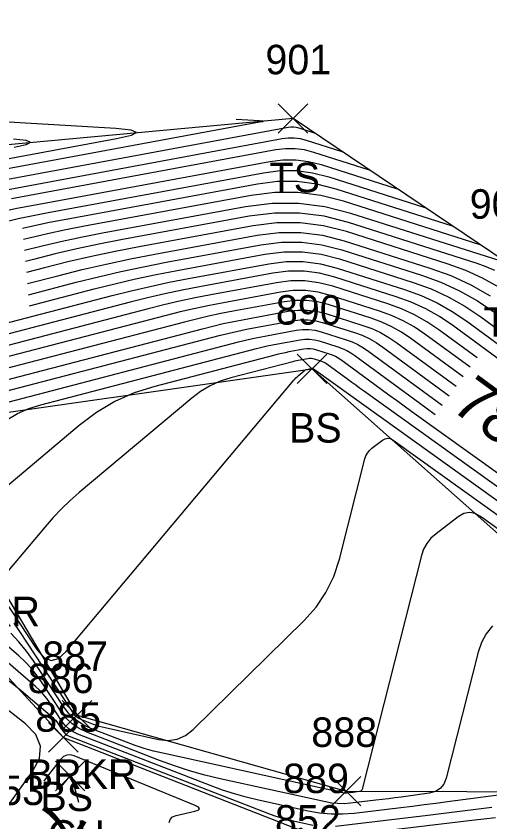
# Model space of a CAD drawing. Extents: x 1650836 to 1652450, y 332578 to 333908.
# Drawn here: x 1652201.2 to 1652233.3, y 332848.3 to 332902.9 of the extents above; entities that cross this region are included whole.
import ezdxf

# ---------------------------------------------------------------- set-up
doc = ezdxf.new("R2010")
doc.units = 0
for name, color, linetype in [('L_A', 7, 'Continuous'), ('L_I', 7, 'Continuous'), ('L_TIC', 7, 'Continuous'), ('LAWE', 7, 'Continuous'), ('LELB', 7, 'Continuous'), ('LSOGCMA', 7, 'Continuous'), ('LSOGCMA_T', 7, 'Continuous'), ('LSOGCMI', 7, 'Continuous'), ('LSOGP', 7, 'Continuous')]:
    doc.layers.add(name, color=color, linetype=linetype)

msp = doc.modelspace()

# ---------------------------------------------------------------- linework, layer by layer
at = {"layer": 'L_TIC'}
for points in [[(1652218.944, 332894.981), (1652220.944, 332896.981)], [(1652220.944, 332894.981), (1652218.944, 332896.981)], [(1652220.23, 332878.003), (1652222.23, 332880.003)], [(1652222.23, 332878.003), (1652220.23, 332880.003)], [(1652204.312, 332854.518), (1652206.312, 332856.518)], [(1652206.312, 332854.518), (1652204.312, 332856.518)], [(1652203.385, 332853.011), (1652205.385, 332855.011)], [(1652205.385, 332853.011), (1652203.385, 332855.011)], [(1652203.839, 332850.394), (1652205.839, 332852.394)], [(1652205.839, 332850.394), (1652203.839, 332852.394)], [(1652222.542, 332849.363), (1652224.542, 332851.363)], [(1652224.542, 332849.363), (1652222.542, 332851.363)]]:
    msp.add_lwpolyline(points, dxfattribs=at)
at = {"layer": 'LAWE'}
msp.add_lwpolyline([(1652166.593, 332836.388), (1652160.434, 332848.646), (1652165.686, 332861.189), (1652174.634, 332867.863), (1652187.273, 332876.813), (1652194.015, 332875.109), (1652198.78, 332866.55), (1652205.312, 332855.518), (1652223.542, 332850.363), (1652239.899, 332850.316), (1652254.339, 332849.604), (1652281.376, 332840.252)], dxfattribs=at)
at = {"layer": 'LELB'}
for points in [[(1652284.715, 332848.326), (1652266.979, 332860.629), (1652252.966, 332867.026), (1652234.442, 332886.186), (1652219.944, 332895.981), (1652193.017, 332893.494), (1652177.262, 332886.323)], [(1652194.015, 332875.109), (1652221.23, 332879.003), (1652254.339, 332849.604)], [(1652273.911, 332830.103), (1652248.33, 332832.215), (1652238.99, 332835.863), (1652205.84, 332837.591), (1652191.874, 332835.507), (1652180.705, 332833.239), (1652166.498, 332840.6), (1652166.784, 332849.708), (1652168.84, 332859.33), (1652177.78, 332865.033), (1652184.593, 332870.407), (1652193.9, 332865.398), (1652204.385, 332854.011), (1652221.637, 332847.232), (1652240.383, 332847.355), (1652253.69, 332847.74), (1652279.741, 332838.109)]]:
    msp.add_lwpolyline(points, dxfattribs=at)
at = {"layer": 'LSOGCMA'}
for points in [[(1652195.942, 332892.392), (1652207.972, 332894.619), (1652209.004, 332894.853), (1652209.341, 332895.044), (1652208.983, 332895.192), (1652207.93, 332895.297), (1652199.524, 332895.797)], [(1652233.605, 332885.664), (1652233.025, 332885.93), (1652232.422, 332886.149), (1652223.711, 332888.93), (1652222.048, 332889.353), (1652220.371, 332889.565), (1652218.681, 332889.566), (1652216.977, 332889.355), (1652208.278, 332887.744), (1652206.787, 332887.454), (1652205.301, 332887.137), (1652203.822, 332886.794), (1652202.349, 332886.424), (1652201.814, 332886.284)], [(1652195.49, 332876.954), (1652213.806, 332881.729), (1652214.509, 332881.906), (1652215.215, 332882.07), (1652215.924, 332882.221), (1652216.636, 332882.359), (1652219.624, 332882.913), (1652220.267, 332882.992), (1652220.906, 332882.992), (1652221.539, 332882.912), (1652222.167, 332882.752), (1652224.67, 332881.953), (1652225.284, 332881.73), (1652225.873, 332881.459), (1652226.439, 332881.141), (1652226.98, 332880.776), (1652230.994, 332877.827)], [(1652234.374, 332850.165), (1652230.41, 332849.631), (1652229.621, 332849.526), (1652228.832, 332849.425), (1652228.043, 332849.326), (1652227.253, 332849.231), (1652224.093, 332848.858), (1652223.304, 332848.798), (1652222.519, 332848.803), (1652221.737, 332848.875), (1652220.959, 332849.014), (1652217.593, 332849.756), (1652216.778, 332849.952), (1652215.972, 332850.179), (1652215.175, 332850.437), (1652214.388, 332850.725), (1652205.374, 332854.227), (1652205.046, 332854.383), (1652204.755, 332854.583), (1652204.498, 332854.827), (1652204.278, 332855.115), (1652203.466, 332856.355), (1652203.254, 332856.656), (1652203.022, 332856.941), (1652202.77, 332857.208), (1652202.499, 332857.459), (1652196.908, 332862.278)], [(1652204.072, 332850.442), (1652204.815, 332851.388), (1652204.826, 332851.399), (1652204.838, 332851.405), (1652204.851, 332851.406), (1652204.866, 332851.402), (1652204.949, 332851.368), (1652204.952, 332851.366), (1652204.953, 332851.365), (1652204.952, 332851.363), (1652204.949, 332851.362), (1652204.933, 332851.359), (1652204.929, 332851.357), (1652204.927, 332851.355), (1652204.926, 332851.352), (1652204.927, 332851.349), (1652205.418, 332849.606)]]:
    msp.add_lwpolyline(points, dxfattribs=at)
at = {"layer": 'LSOGCMI'}
for points in [[(1652216.085, 332895.946), (1652217.674, 332895.852), (1652217.873, 332895.832), (1652217.94, 332895.804), (1652217.877, 332895.768), (1652217.681, 332895.724), (1652197.176, 332891.927)], [(1652198.409, 332891.462), (1652219.623, 332895.39), (1652219.802, 332895.412), (1652219.98, 332895.412), (1652220.157, 332895.39), (1652220.332, 332895.345), (1652221.379, 332895.011)], [(1652199.643, 332890.997), (1652219.205, 332894.62), (1652219.619, 332894.671), (1652220.029, 332894.671), (1652220.435, 332894.619), (1652220.839, 332894.517), (1652223.251, 332893.747)], [(1652201.04, 332894.029), (1652201.871, 332894.217), (1652202.142, 332894.371), (1652201.854, 332894.49), (1652201.006, 332894.574)], [(1652225.123, 332892.482), (1652221.346, 332893.688), (1652220.714, 332893.849), (1652220.077, 332893.929), (1652219.435, 332893.929), (1652218.787, 332893.849), (1652200.877, 332890.533)], [(1652195.425, 332888.459), (1652198.577, 332889.281), (1652199.455, 332889.502), (1652200.337, 332889.706), (1652201.222, 332889.895), (1652202.11, 332890.068), (1652218.37, 332893.078), (1652219.251, 332893.188), (1652220.125, 332893.187), (1652220.992, 332893.078), (1652221.853, 332892.859), (1652226.994, 332891.218)], [(1652199.958, 332888.867), (1652200.328, 332888.96), (1652201.33, 332889.193), (1652202.335, 332889.407), (1652203.344, 332889.603), (1652217.952, 332892.308), (1652219.067, 332892.446), (1652220.173, 332892.446), (1652221.271, 332892.307), (1652222.359, 332892.03), (1652228.866, 332889.953)], [(1652230.738, 332888.688), (1652222.866, 332891.201), (1652221.549, 332891.536), (1652220.221, 332891.704), (1652218.883, 332891.704), (1652217.534, 332891.537), (1652204.577, 332889.138), (1652203.448, 332888.919), (1652202.322, 332888.679), (1652201.613, 332888.514)], [(1652232.61, 332887.424), (1652223.373, 332890.372), (1652221.827, 332890.766), (1652220.269, 332890.962), (1652218.699, 332890.963), (1652217.116, 332890.767), (1652205.811, 332888.673), (1652204.561, 332888.43), (1652203.315, 332888.165), (1652202.075, 332887.877), (1652201.679, 332887.778)], [(1652234.506, 332886.138), (1652234.504, 332886.137), (1652234.51, 332886.119), (1652234.51, 332886.117), (1652234.51, 332886.116), (1652234.509, 332886.116), (1652234.507, 332886.117), (1652234.447, 332886.161), (1652234.436, 332886.169), (1652234.424, 332886.175), (1652234.412, 332886.181), (1652234.399, 332886.185), (1652223.866, 332889.548), (1652222.099, 332889.997), (1652220.318, 332890.222), (1652218.522, 332890.223), (1652216.713, 332889.999), (1652207.044, 332888.209), (1652205.674, 332887.942), (1652204.308, 332887.651), (1652202.949, 332887.335), (1652201.746, 332887.033)], [(1652233.885, 332884.534), (1652232.785, 332885.153), (1652231.639, 332885.679), (1652230.445, 332886.114), (1652223.557, 332888.312), (1652221.997, 332888.709), (1652220.424, 332888.908), (1652218.84, 332888.908), (1652217.242, 332888.71), (1652209.512, 332887.279), (1652207.9, 332886.966), (1652206.294, 332886.623), (1652204.695, 332886.252), (1652203.103, 332885.852), (1652201.881, 332885.534)], [(1652201.949, 332884.783), (1652204.019, 332885.323), (1652205.65, 332885.732), (1652207.287, 332886.112), (1652208.93, 332886.463), (1652210.58, 332886.784), (1652217.507, 332888.066), (1652218.998, 332888.251), (1652220.478, 332888.251), (1652221.946, 332888.065), (1652223.402, 332887.695), (1652229.205, 332885.842), (1652230.627, 332885.325), (1652231.994, 332884.697), (1652233.305, 332883.96)], [(1652202.016, 332884.033), (1652205.243, 332884.874), (1652206.757, 332885.254), (1652208.278, 332885.607), (1652209.805, 332885.933), (1652211.337, 332886.231), (1652217.771, 332887.422), (1652219.157, 332887.594), (1652220.531, 332887.593), (1652221.895, 332887.421), (1652223.248, 332887.077), (1652228.638, 332885.356), (1652229.959, 332884.875), (1652231.229, 332884.292), (1652232.447, 332883.607), (1652233.612, 332882.821)], [(1652202.084, 332883.282), (1652206.466, 332884.425), (1652207.865, 332884.776), (1652209.269, 332885.102), (1652210.679, 332885.402), (1652212.094, 332885.678), (1652218.036, 332886.778), (1652219.315, 332886.936), (1652220.585, 332886.936), (1652221.844, 332886.777), (1652223.094, 332886.459), (1652228.071, 332884.87), (1652229.291, 332884.426), (1652230.464, 332883.888), (1652231.588, 332883.255), (1652232.665, 332882.529), (1652249.811, 332869.928)], [(1652194.937, 332880.651), (1652207.689, 332883.975), (1652208.972, 332884.298), (1652210.26, 332884.596), (1652211.553, 332884.872), (1652212.851, 332885.125), (1652218.301, 332886.134), (1652219.474, 332886.279), (1652220.638, 332886.279), (1652221.793, 332886.133), (1652222.939, 332885.841), (1652227.504, 332884.384), (1652228.624, 332883.977), (1652229.699, 332883.483), (1652230.73, 332882.903), (1652231.717, 332882.237), (1652251.546, 332867.665)], [(1652248.076, 332869.227), (1652230.77, 332881.944), (1652229.872, 332882.551), (1652228.934, 332883.078), (1652227.956, 332883.527), (1652226.937, 332883.898), (1652222.785, 332885.223), (1652221.742, 332885.489), (1652220.692, 332885.621), (1652219.633, 332885.622), (1652218.565, 332885.489), (1652213.608, 332884.572), (1652212.427, 332884.342), (1652211.251, 332884.091), (1652210.079, 332883.819), (1652208.912, 332883.526), (1652195.048, 332879.911)], [(1652232.407, 332879.753), (1652229.823, 332881.652), (1652229.014, 332882.198), (1652228.169, 332882.673), (1652227.288, 332883.078), (1652226.371, 332883.412), (1652222.63, 332884.606), (1652221.692, 332884.845), (1652220.745, 332884.964), (1652219.791, 332884.964), (1652218.83, 332884.845), (1652214.365, 332884.019), (1652213.302, 332883.812), (1652212.242, 332883.586), (1652211.187, 332883.341), (1652210.136, 332883.077), (1652195.158, 332879.172)], [(1652231.936, 332879.111), (1652228.875, 332881.36), (1652228.155, 332881.846), (1652227.404, 332882.269), (1652226.62, 332882.629), (1652225.804, 332882.926), (1652222.476, 332883.988), (1652221.641, 332884.2), (1652220.799, 332884.307), (1652219.95, 332884.307), (1652219.095, 332884.201), (1652215.122, 332883.466), (1652214.176, 332883.281), (1652213.233, 332883.081), (1652212.294, 332882.863), (1652211.359, 332882.628), (1652195.269, 332878.433)], [(1652231.465, 332878.469), (1652227.928, 332881.068), (1652227.297, 332881.494), (1652226.638, 332881.864), (1652225.952, 332882.179), (1652225.237, 332882.44), (1652222.322, 332883.37), (1652221.59, 332883.556), (1652220.852, 332883.649), (1652220.109, 332883.65), (1652219.359, 332883.557), (1652215.879, 332882.912), (1652215.05, 332882.751), (1652214.224, 332882.575), (1652213.402, 332882.384), (1652212.582, 332882.179), (1652195.379, 332877.693)], [(1652195.601, 332876.215), (1652215.029, 332881.28), (1652215.617, 332881.428), (1652216.206, 332881.565), (1652216.799, 332881.691), (1652217.393, 332881.806), (1652219.889, 332882.268), (1652220.426, 332882.335), (1652220.959, 332882.335), (1652221.488, 332882.268), (1652222.013, 332882.135), (1652224.103, 332881.467), (1652224.616, 332881.281), (1652225.108, 332881.055), (1652225.58, 332880.789), (1652226.033, 332880.484), (1652230.522, 332877.185)], [(1652194.813, 332875.241), (1652216.252, 332880.831), (1652216.724, 332880.949), (1652217.197, 332881.059), (1652217.673, 332881.161), (1652218.15, 332881.253), (1652220.153, 332881.624), (1652220.585, 332881.678), (1652221.013, 332881.678), (1652221.437, 332881.624), (1652221.858, 332881.517), (1652223.536, 332880.981), (1652223.948, 332880.831), (1652224.343, 332880.65), (1652224.722, 332880.437), (1652225.085, 332880.192), (1652230.051, 332876.542)], [(1652200.554, 332875.539), (1652201.279, 332875.968), (1652202.048, 332876.311), (1652202.86, 332876.571), (1652217.476, 332880.382), (1652217.831, 332880.471), (1652218.189, 332880.554), (1652218.547, 332880.63), (1652218.907, 332880.7), (1652220.418, 332880.98), (1652220.743, 332881.02), (1652221.066, 332881.02), (1652221.386, 332880.98), (1652221.704, 332880.899), (1652222.97, 332880.495), (1652223.28, 332880.382), (1652223.578, 332880.245), (1652223.864, 332880.084), (1652224.138, 332879.9), (1652228.187, 332876.924), (1652228.952, 332876.363), (1652229.583, 332875.904)], [(1652251.835, 332858.989), (1652227.989, 332876.099), (1652227.47, 332876.472), (1652226.952, 332876.847), (1652226.436, 332877.224), (1652225.92, 332877.601), (1652223.19, 332879.607), (1652223.006, 332879.732), (1652222.813, 332879.84), (1652222.612, 332879.933), (1652222.403, 332880.009), (1652221.549, 332880.281), (1652221.335, 332880.336), (1652221.119, 332880.363), (1652220.902, 332880.363), (1652220.682, 332880.336), (1652219.664, 332880.147), (1652219.421, 332880.1), (1652219.18, 332880.049), (1652218.939, 332879.993), (1652218.699, 332879.932), (1652210.585, 332877.817), (1652209.191, 332877.371), (1652207.871, 332876.781), (1652206.626, 332876.046), (1652205.456, 332875.166), (1652198.656, 332869.449)], [(1652252.145, 332857.826), (1652224.722, 332877.503), (1652224.454, 332877.696), (1652224.187, 332877.889), (1652223.92, 332878.084), (1652223.653, 332878.279), (1652222.243, 332879.315), (1652222.147, 332879.38), (1652222.048, 332879.436), (1652221.944, 332879.483), (1652221.836, 332879.523), (1652221.395, 332879.663), (1652221.284, 332879.692), (1652221.173, 332879.706), (1652221.06, 332879.706), (1652220.947, 332879.692), (1652220.421, 332879.594), (1652220.296, 332879.57), (1652220.171, 332879.543), (1652220.046, 332879.514), (1652219.922, 332879.483), (1652215.73, 332878.39), (1652215.01, 332878.16), (1652214.328, 332877.855), (1652213.685, 332877.475), (1652213.08, 332877.021), (1652205.461, 332870.616), (1652204.845, 332870.074), (1652204.254, 332869.508), (1652203.688, 332868.916), (1652203.148, 332868.299), (1652200.254, 332864.846)], [(1652200.292, 332863.478), (1652202.596, 332859.959), (1652203.063, 332859.428), (1652203.549, 332859.231), (1652204.056, 332859.369), (1652204.582, 332859.841), (1652219.997, 332878.232), (1652220.066, 332878.312), (1652220.139, 332878.388), (1652220.215, 332878.461), (1652220.295, 332878.53), (1652220.705, 332878.875), (1652220.744, 332878.905), (1652220.785, 332878.929), (1652220.829, 332878.949), (1652220.876, 332878.964), (1652221.146, 332879.034), (1652221.154, 332879.036), (1652221.162, 332879.038), (1652221.17, 332879.04), (1652221.178, 332879.041), (1652221.212, 332879.047), (1652221.219, 332879.048), (1652221.226, 332879.048), (1652221.234, 332879.047), (1652221.241, 332879.046), (1652221.269, 332879.037), (1652221.276, 332879.034), (1652221.283, 332879.031), (1652221.289, 332879.027), (1652221.295, 332879.023), (1652221.386, 332878.956), (1652221.403, 332878.944), (1652221.421, 332878.931), (1652221.438, 332878.919), (1652221.455, 332878.906), (1652252.456, 332856.663)], [(1652201.02, 332861.754), (1652201.42, 332861.187), (1652204.992, 332855.729), (1652205.118, 332855.564), (1652205.265, 332855.425), (1652205.432, 332855.31), (1652205.619, 332855.221), (1652206.409, 332854.914), (1652206.608, 332854.841), (1652206.809, 332854.776), (1652207.012, 332854.719), (1652207.218, 332854.67), (1652210.838, 332853.871), (1652211.488, 332853.802), (1652212.093, 332853.89), (1652212.652, 332854.136), (1652213.166, 332854.54), (1652220.689, 332861.928), (1652221.505, 332862.843), (1652222.176, 332863.841), (1652222.701, 332864.924), (1652223.08, 332866.09), (1652224.805, 332872.896), (1652224.876, 332873.107), (1652224.979, 332873.297), (1652225.114, 332873.466), (1652225.28, 332873.614), (1652226.005, 332874.165), (1652226.187, 332874.269), (1652226.37, 332874.306), (1652226.553, 332874.274), (1652226.738, 332874.175), (1652252.766, 332855.5)], [(1652253.077, 332854.337), (1652232.654, 332868.991), (1652232.271, 332869.196), (1652231.89, 332869.261), (1652231.511, 332869.185), (1652231.133, 332868.97), (1652229.629, 332867.826), (1652229.285, 332867.519), (1652229.006, 332867.168), (1652228.793, 332866.775), (1652228.644, 332866.338), (1652224.631, 332850.504), (1652224.606, 332850.44), (1652224.567, 332850.391), (1652224.514, 332850.358), (1652224.447, 332850.34), (1652224.142, 332850.299), (1652224.073, 332850.29), (1652224.004, 332850.281), (1652223.935, 332850.272), (1652223.866, 332850.264), (1652223.59, 332850.231), (1652223.521, 332850.226), (1652223.453, 332850.227), (1652223.384, 332850.233), (1652223.316, 332850.245), (1652211.113, 332852.935), (1652210.487, 332853.086), (1652209.868, 332853.26), (1652209.256, 332853.458), (1652208.651, 332853.68), (1652206.246, 332854.614), (1652205.676, 332854.886), (1652205.168, 332855.235), (1652204.722, 332855.659), (1652204.338, 332856.161), (1652202.354, 332859.191), (1652201.884, 332859.857), (1652201.372, 332860.486), (1652200.816, 332861.076)], [(1652233.456, 332861.571), (1652233.033, 332861.039), (1652232.709, 332860.442), (1652232.483, 332859.78), (1652230.32, 332851.243), (1652230.163, 332850.842), (1652229.919, 332850.538), (1652229.59, 332850.331), (1652229.174, 332850.221), (1652227.276, 332849.965), (1652226.847, 332849.908), (1652226.418, 332849.853), (1652225.989, 332849.799), (1652225.56, 332849.748), (1652223.841, 332849.545), (1652223.413, 332849.512), (1652222.986, 332849.515), (1652222.561, 332849.554), (1652222.138, 332849.629), (1652215.009, 332851.201), (1652213.962, 332851.453), (1652212.927, 332851.744), (1652211.904, 332852.075), (1652210.893, 332852.446), (1652205.972, 332854.358), (1652205.446, 332854.608), (1652204.978, 332854.93), (1652204.567, 332855.321), (1652204.213, 332855.783), (1652202.91, 332857.773), (1652202.569, 332858.257), (1652202.197, 332858.713), (1652201.793, 332859.142), (1652201.358, 332859.544), (1652194.566, 332865.399)], [(1652194.299, 332862.616), (1652200.46, 332858.031), (1652200.813, 332857.763), (1652201.162, 332857.488), (1652201.506, 332857.208), (1652201.845, 332856.921), (1652203.64, 332855.373), (1652203.747, 332855.274), (1652203.847, 332855.168), (1652203.938, 332855.056), (1652204.022, 332854.937), (1652204.343, 332854.447), (1652204.43, 332854.334), (1652204.531, 332854.237), (1652204.647, 332854.158), (1652204.776, 332854.096), (1652218.277, 332848.851), (1652218.642, 332848.717), (1652219.011, 332848.598), (1652219.385, 332848.493), (1652219.763, 332848.402), (1652221.283, 332848.067)], [(1652198.481, 332844.753), (1652198.384, 332845.524), (1652198.372, 332845.837), (1652198.418, 332846.135), (1652198.521, 332846.419), (1652198.681, 332846.688), (1652202.288, 332851.69), (1652202.757, 332852.583), (1652202.837, 332853.42), (1652202.527, 332854.202), (1652201.827, 332854.929), (1652192.872, 332861.92)], [(1652211.549, 332848.231), (1652211.611, 332848.451), (1652211.774, 332848.612), (1652212.036, 332848.714), (1652213.283, 332849.003), (1652213.518, 332849.081), (1652213.602, 332849.172), (1652213.534, 332849.275), (1652213.314, 332849.391), (1652205.122, 332852.756), (1652204.854, 332852.826), (1652204.61, 332852.809), (1652204.388, 332852.703), (1652204.19, 332852.51), (1652203.444, 332851.56), (1652203.259, 332851.321), (1652203.076, 332851.081), (1652203.066, 332851.067)], [(1652222.816, 332847.99), (1652229.073, 332848.73), (1652230.16, 332848.861), (1652231.246, 332848.996), (1652232.332, 332849.135), (1652233.417, 332849.279)], [(1652233.66, 332848.562), (1652232.861, 332848.463), (1652232.062, 332848.367), (1652222.801, 332847.272)]]:
    msp.add_lwpolyline(points, dxfattribs=at)
at = {"layer": 'LSOGP'}
msp.add_lwpolyline([(1652322.392, 332778.396), (1652286.244, 332816.269), (1652278.684, 332833.467), (1652279.741, 332838.109), (1652281.376, 332840.252), (1652284.715, 332848.326), (1652266.979, 332860.629), (1652252.966, 332867.026), (1652234.442, 332886.186), (1652219.944, 332895.981), (1652193.017, 332893.494), (1652163.094, 332891.822), (1652141.158, 332895.272), (1652101.604, 332894.697), (1652074.965, 332899.016), (1652042.229, 332910.088), (1652009.557, 332917.982), (1651992.258, 332920.35), (1651945.495, 332936.417)], dxfattribs=at)

# ---------------------------------------------------------------- texts
at = {"layer": 'L_A'}
for s, p in [('TS', (1652218.353, 332890.981)), ('TS', (1652232.851, 332881.186)), ('BS', (1652219.671, 332874.003)), ('BRKR', (1652195.371, 332861.55)), ('BRKR', (1652201.903, 332850.518)), ('BS', (1652202.826, 332849.011)), ('CH', (1652203.327, 332846.394))]:
    msp.add_text(s, height=2, dxfattribs=at).set_placement(p)
at = {"layer": 'L_I'}
for s, p in [('901', (1652218.07, 332898.981)), ('900', (1652231.914, 332889.186)), ('890', (1652218.781, 332882.003)), ('887', (1652202.95, 332858.518)), ('886', (1652201.968, 332857.011)), ('885', (1652202.477, 332854.394)), ('888', (1652221.18, 332853.363)), ('889', (1652219.267, 332850.232)), ('853', (1652198.615, 332849.421)), ('852', (1652218.721, 332847.413))]:
    msp.add_text(s, height=2, dxfattribs=at).set_placement(p)
at = {"layer": 'LSOGCMA_T'}
for s, rotation, p in [('780', 323.724, (1652230.545, 332876.297)), ('775', 238.1521, (1652203.507, 332850.001))]:
    msp.add_text(s, height=3, rotation=rotation, dxfattribs=at).set_placement(p)

doc.saveas('drawing.dxf')
